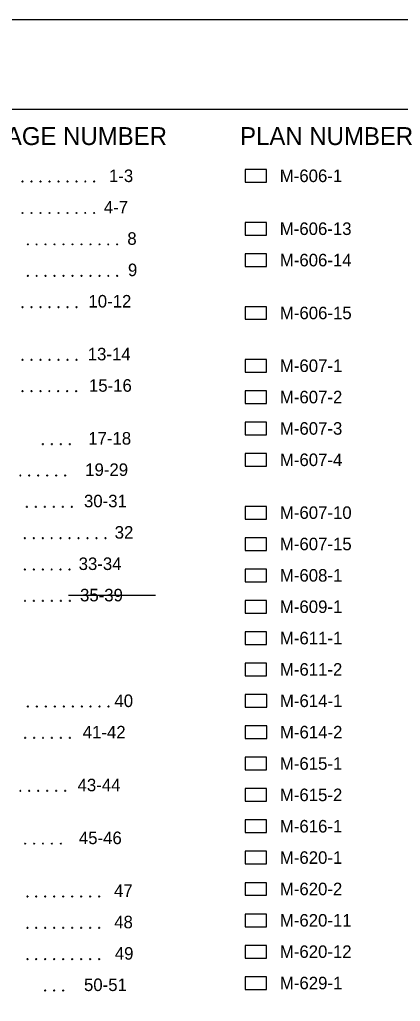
# Model space of a CAD drawing. Extents: x 0 to 1.42, y 0 to 0.92.
# Drawn here: x 0.4322 to 0.6093, y 0.4598 to 0.9167 of the extents above; entities that cross this region are included whole.
import ezdxf

# ---------------------------------------------------------------- set-up
doc = ezdxf.new("R2010")
doc.units = 0
for name, color, linetype in [('DRAFT_Text-Notes', 7, 'Continuous'), ('DRAFT_Text-Titles', 7, 'Continuous'), ('SHEET_Lines', 7, 'Continuous'), ('SHEET_Plot Boundary', 7, 'Continuous')]:
    doc.layers.add(name, color=color, linetype=linetype)

msp = doc.modelspace()

# ---------------------------------------------------------------- linework, layer by layer
at = {"layer": 'DRAFT_Text-Notes'}
for centre in [(0.43359, 0.84128), (0.43776, 0.84128), (0.44192, 0.84128), (0.44609, 0.84128), (0.45026, 0.84128), (0.45442, 0.84128), (0.45859, 0.84128), (0.46276, 0.84128), (0.46692, 0.84128), (0.43359, 0.82669), (0.43776, 0.82669), (0.44192, 0.82669), (0.44609, 0.82669), (0.45026, 0.82669), (0.45442, 0.82669), (0.45859, 0.82669), (0.46276, 0.82669), (0.46692, 0.82669), (0.43596, 0.8121), (0.44013, 0.8121), (0.44429, 0.8121), (0.44846, 0.8121), (0.45263, 0.8121), (0.45679, 0.8121), (0.46096, 0.8121), (0.46513, 0.8121), (0.46929, 0.8121), (0.47346, 0.8121), (0.47763, 0.8121), (0.43596, 0.79751), (0.44013, 0.79751), (0.44429, 0.79751), (0.44846, 0.79751), (0.45263, 0.79751), (0.45679, 0.79751), (0.46096, 0.79751), (0.46513, 0.79751), (0.46929, 0.79751), (0.47346, 0.79751), (0.47763, 0.79751), (0.43359, 0.78292), (0.43776, 0.78292), (0.44192, 0.78292), (0.44609, 0.78292), (0.45026, 0.78292), (0.45442, 0.78292), (0.45859, 0.78292), (0.43359, 0.75832), (0.43776, 0.75832), (0.44192, 0.75832), (0.44609, 0.75832), (0.45026, 0.75832), (0.45442, 0.75832), (0.45859, 0.75832), (0.43352, 0.74373), (0.43769, 0.74373), (0.44185, 0.74373), (0.44602, 0.74373), (0.45019, 0.74373), (0.45435, 0.74373), (0.45852, 0.74373), (0.44306, 0.71914), (0.44722, 0.71914), (0.45139, 0.71914), (0.45556, 0.71914), (0.43253, 0.70455), (0.4367, 0.70455), (0.44086, 0.70455), (0.44503, 0.70455), (0.4492, 0.70455), (0.45336, 0.70455), (0.43561, 0.68996), (0.43978, 0.68996), (0.44394, 0.68996), (0.44811, 0.68996), (0.45228, 0.68996), (0.45644, 0.68996), (0.4346, 0.67536), (0.43877, 0.67536), (0.44293, 0.67536), (0.4471, 0.67536), (0.45127, 0.67536), (0.45543, 0.67536), (0.4596, 0.67536), (0.46377, 0.67536), (0.46793, 0.67536), (0.4721, 0.67536), (0.4346, 0.66077), (0.43877, 0.66077), (0.44293, 0.66077), (0.4471, 0.66077), (0.45127, 0.66077), (0.45543, 0.66077), (0.43471, 0.64618), (0.43887, 0.64618), (0.44304, 0.64618), (0.44721, 0.64618), (0.45137, 0.64618), (0.45554, 0.64618), (0.43607, 0.597), (0.44023, 0.597), (0.4444, 0.597), (0.44857, 0.597), (0.45273, 0.597), (0.4569, 0.597), (0.46107, 0.597), (0.46523, 0.597), (0.4694, 0.597), (0.47357, 0.597), (0.43474, 0.5824), (0.43891, 0.5824), (0.44307, 0.5824), (0.44724, 0.5824), (0.45141, 0.5824), (0.45557, 0.5824), (0.43253, 0.55781), (0.4367, 0.55781), (0.44087, 0.55781), (0.44503, 0.55781), (0.4492, 0.55781), (0.45337, 0.55781), (0.43474, 0.53322), (0.43891, 0.53322), (0.44307, 0.53322), (0.44724, 0.53322), (0.45141, 0.53322), (0.4358, 0.50863), (0.43996, 0.50863), (0.44413, 0.50863), (0.4483, 0.50863), (0.45246, 0.50863), (0.45663, 0.50863), (0.4608, 0.50863), (0.46496, 0.50863), (0.46913, 0.50863), (0.4358, 0.49404), (0.43996, 0.49404), (0.44413, 0.49404), (0.4483, 0.49404), (0.45246, 0.49404), (0.45663, 0.49404), (0.4608, 0.49404), (0.46496, 0.49404), (0.46913, 0.49404), (0.4358, 0.47944), (0.43996, 0.47944), (0.44413, 0.47944), (0.4483, 0.47944), (0.45246, 0.47944), (0.45663, 0.47944), (0.4608, 0.47944), (0.46496, 0.47944), (0.46913, 0.47944), (0.44413, 0.46485), (0.4483, 0.46485), (0.45246, 0.46485)]:
    msp.add_circle(centre, 0.000208, dxfattribs=at)
for centre, start, end in [((0.43359, 0.84128), 0, 180), ((0.43359, 0.84128), 180, 0), ((0.43776, 0.84128), 0, 180), ((0.43776, 0.84128), 180, 0), ((0.44192, 0.84128), 0, 180), ((0.44192, 0.84128), 180, 0), ((0.44609, 0.84128), 0, 180), ((0.44609, 0.84128), 180, 0), ((0.45026, 0.84128), 0, 180), ((0.45026, 0.84128), 180, 0), ((0.45442, 0.84128), 0, 180), ((0.45442, 0.84128), 180, 0), ((0.45859, 0.84128), 0, 180), ((0.45859, 0.84128), 180, 0), ((0.46276, 0.84128), 0, 180), ((0.46276, 0.84128), 180, 0), ((0.46692, 0.84128), 0, 180), ((0.46692, 0.84128), 180, 0), ((0.43359, 0.82669), 0, 180), ((0.43776, 0.82669), 0, 180), ((0.44192, 0.82669), 0, 180), ((0.44609, 0.82669), 0, 180), ((0.45026, 0.82669), 0, 180), ((0.45442, 0.82669), 0, 180), ((0.45859, 0.82669), 0, 180), ((0.46276, 0.82669), 0, 180), ((0.46692, 0.82669), 0, 180), ((0.43359, 0.82669), 180, 0), ((0.43776, 0.82669), 180, 0), ((0.44192, 0.82669), 180, 0), ((0.44609, 0.82669), 180, 0), ((0.45026, 0.82669), 180, 0), ((0.45442, 0.82669), 180, 0), ((0.45859, 0.82669), 180, 0), ((0.46276, 0.82669), 180, 0), ((0.46692, 0.82669), 180, 0), ((0.43596, 0.8121), 0, 180), ((0.43596, 0.8121), 180, 0), ((0.44013, 0.8121), 0, 180), ((0.44013, 0.8121), 180, 0), ((0.44429, 0.8121), 0, 180), ((0.44429, 0.8121), 180, 0), ((0.44846, 0.8121), 0, 180), ((0.44846, 0.8121), 180, 0), ((0.45263, 0.8121), 0, 180), ((0.45263, 0.8121), 180, 0), ((0.45679, 0.8121), 0, 180), ((0.45679, 0.8121), 180, 0), ((0.46096, 0.8121), 0, 180), ((0.46096, 0.8121), 180, 0), ((0.46513, 0.8121), 0, 180), ((0.46513, 0.8121), 180, 0), ((0.46929, 0.8121), 0, 180), ((0.46929, 0.8121), 180, 0), ((0.47346, 0.8121), 0, 180), ((0.47346, 0.8121), 180, 0), ((0.47763, 0.8121), 0, 180), ((0.47763, 0.8121), 180, 0), ((0.43596, 0.79751), 0, 180), ((0.43596, 0.79751), 180, 0), ((0.44013, 0.79751), 0, 180), ((0.44013, 0.79751), 180, 0), ((0.44429, 0.79751), 0, 180), ((0.44429, 0.79751), 180, 0), ((0.44846, 0.79751), 0, 180), ((0.44846, 0.79751), 180, 0), ((0.45263, 0.79751), 0, 180), ((0.45263, 0.79751), 180, 0), ((0.45679, 0.79751), 0, 180), ((0.45679, 0.79751), 180, 0), ((0.46096, 0.79751), 0, 180), ((0.46096, 0.79751), 180, 0), ((0.46513, 0.79751), 0, 180), ((0.46513, 0.79751), 180, 0), ((0.46929, 0.79751), 0, 180), ((0.46929, 0.79751), 180, 0), ((0.47346, 0.79751), 0, 180), ((0.47346, 0.79751), 180, 0), ((0.47763, 0.79751), 0, 180), ((0.47763, 0.79751), 180, 0), ((0.43359, 0.78292), 0, 180), ((0.43359, 0.78292), 180, 0), ((0.43776, 0.78292), 0, 180), ((0.43776, 0.78292), 180, 0), ((0.44192, 0.78292), 0, 180), ((0.44192, 0.78292), 180, 0), ((0.44609, 0.78292), 0, 180), ((0.44609, 0.78292), 180, 0), ((0.45026, 0.78292), 0, 180), ((0.45026, 0.78292), 180, 0), ((0.45442, 0.78292), 0, 180), ((0.45442, 0.78292), 180, 0), ((0.45859, 0.78292), 0, 180), ((0.45859, 0.78292), 180, 0), ((0.43359, 0.75832), 0, 180), ((0.43776, 0.75832), 0, 180), ((0.44192, 0.75832), 0, 180), ((0.44609, 0.75832), 0, 180), ((0.45026, 0.75832), 0, 180), ((0.45442, 0.75832), 0, 180), ((0.45859, 0.75832), 0, 180), ((0.43359, 0.75832), 180, 0), ((0.43776, 0.75832), 180, 0), ((0.44192, 0.75832), 180, 0), ((0.44609, 0.75832), 180, 0), ((0.45026, 0.75832), 180, 0), ((0.45442, 0.75832), 180, 0), ((0.45859, 0.75832), 180, 0), ((0.43352, 0.74373), 0, 180), ((0.43352, 0.74373), 180, 0), ((0.43769, 0.74373), 0, 180), ((0.43769, 0.74373), 180, 0), ((0.44185, 0.74373), 0, 180), ((0.44185, 0.74373), 180, 0), ((0.44602, 0.74373), 0, 180), ((0.44602, 0.74373), 180, 0), ((0.45019, 0.74373), 0, 180), ((0.45019, 0.74373), 180, 0), ((0.45435, 0.74373), 0, 180), ((0.45435, 0.74373), 180, 0), ((0.45852, 0.74373), 0, 180), ((0.45852, 0.74373), 180, 0), ((0.44306, 0.71914), 0, 180), ((0.44306, 0.71914), 180, 0), ((0.44722, 0.71914), 0, 180), ((0.44722, 0.71914), 180, 0), ((0.45139, 0.71914), 0, 180), ((0.45139, 0.71914), 180, 0), ((0.45556, 0.71914), 0, 180), ((0.45556, 0.71914), 180, 0), ((0.43253, 0.70455), 0, 180), ((0.43253, 0.70455), 180, 0), ((0.4367, 0.70455), 0, 180), ((0.4367, 0.70455), 180, 0), ((0.44086, 0.70455), 0, 180), ((0.44086, 0.70455), 180, 0), ((0.44503, 0.70455), 0, 180), ((0.44503, 0.70455), 180, 0), ((0.4492, 0.70455), 0, 180), ((0.4492, 0.70455), 180, 0), ((0.45336, 0.70455), 0, 180), ((0.45336, 0.70455), 180, 0), ((0.43561, 0.68996), 0, 180), ((0.43561, 0.68996), 180, 0), ((0.43978, 0.68996), 0, 180), ((0.43978, 0.68996), 180, 0), ((0.44394, 0.68996), 0, 180), ((0.44394, 0.68996), 180, 0), ((0.44811, 0.68996), 0, 180), ((0.44811, 0.68996), 180, 0), ((0.45228, 0.68996), 0, 180), ((0.45228, 0.68996), 180, 0), ((0.45644, 0.68996), 0, 180), ((0.45644, 0.68996), 180, 0), ((0.4346, 0.67536), 0, 180), ((0.4346, 0.67536), 180, 0), ((0.43877, 0.67536), 0, 180), ((0.43877, 0.67536), 180, 0), ((0.44293, 0.67536), 0, 180), ((0.44293, 0.67536), 180, 0), ((0.4471, 0.67536), 0, 180), ((0.4471, 0.67536), 180, 0), ((0.45127, 0.67536), 0, 180), ((0.45127, 0.67536), 180, 0), ((0.45543, 0.67536), 0, 180), ((0.45543, 0.67536), 180, 0), ((0.4596, 0.67536), 0, 180), ((0.4596, 0.67536), 180, 0), ((0.46377, 0.67536), 0, 180), ((0.46377, 0.67536), 180, 0), ((0.46793, 0.67536), 0, 180), ((0.46793, 0.67536), 180, 0), ((0.4721, 0.67536), 0, 180), ((0.4721, 0.67536), 180, 0), ((0.4346, 0.66077), 0, 180), ((0.4346, 0.66077), 180, 0), ((0.43877, 0.66077), 0, 180), ((0.43877, 0.66077), 180, 0), ((0.44293, 0.66077), 0, 180), ((0.44293, 0.66077), 180, 0), ((0.4471, 0.66077), 0, 180), ((0.4471, 0.66077), 180, 0), ((0.45127, 0.66077), 0, 180), ((0.45127, 0.66077), 180, 0), ((0.45543, 0.66077), 0, 180), ((0.45543, 0.66077), 180, 0), ((0.43471, 0.64618), 0, 180), ((0.43471, 0.64618), 180, 0), ((0.43887, 0.64618), 0, 180), ((0.43887, 0.64618), 180, 0), ((0.44304, 0.64618), 0, 180), ((0.44304, 0.64618), 180, 0), ((0.44721, 0.64618), 0, 180), ((0.44721, 0.64618), 180, 0), ((0.45137, 0.64618), 0, 180), ((0.45137, 0.64618), 180, 0), ((0.45554, 0.64618), 0, 180), ((0.45554, 0.64618), 180, 0), ((0.43607, 0.597), 0, 180), ((0.43607, 0.597), 180, 0), ((0.44023, 0.597), 0, 180), ((0.44023, 0.597), 180, 0), ((0.4444, 0.597), 0, 180), ((0.4444, 0.597), 180, 0), ((0.44857, 0.597), 0, 180), ((0.44857, 0.597), 180, 0), ((0.45273, 0.597), 0, 180), ((0.45273, 0.597), 180, 0), ((0.4569, 0.597), 0, 180), ((0.4569, 0.597), 180, 0), ((0.46107, 0.597), 0, 180), ((0.46107, 0.597), 180, 0), ((0.46523, 0.597), 0, 180), ((0.46523, 0.597), 180, 0), ((0.4694, 0.597), 0, 180), ((0.4694, 0.597), 180, 0), ((0.47357, 0.597), 0, 180), ((0.47357, 0.597), 180, 0), ((0.43474, 0.5824), 0, 180), ((0.43474, 0.5824), 180, 0), ((0.43891, 0.5824), 0, 180), ((0.43891, 0.5824), 180, 0), ((0.44307, 0.5824), 0, 180), ((0.44307, 0.5824), 180, 0), ((0.44724, 0.5824), 0, 180), ((0.44724, 0.5824), 180, 0), ((0.45141, 0.5824), 0, 180), ((0.45141, 0.5824), 180, 0), ((0.45557, 0.5824), 0, 180), ((0.45557, 0.5824), 180, 0), ((0.43253, 0.55781), 0, 180), ((0.43253, 0.55781), 180, 0), ((0.4367, 0.55781), 0, 180), ((0.4367, 0.55781), 180, 0), ((0.44087, 0.55781), 0, 180), ((0.44087, 0.55781), 180, 0), ((0.44503, 0.55781), 0, 180), ((0.44503, 0.55781), 180, 0), ((0.4492, 0.55781), 0, 180), ((0.4492, 0.55781), 180, 0), ((0.45337, 0.55781), 0, 180), ((0.45337, 0.55781), 180, 0), ((0.43474, 0.53322), 0, 180), ((0.43474, 0.53322), 180, 0), ((0.43891, 0.53322), 0, 180), ((0.43891, 0.53322), 180, 0), ((0.44307, 0.53322), 0, 180), ((0.44307, 0.53322), 180, 0), ((0.44724, 0.53322), 0, 180), ((0.44724, 0.53322), 180, 0), ((0.45141, 0.53322), 0, 180), ((0.45141, 0.53322), 180, 0), ((0.4358, 0.50863), 0, 180), ((0.4358, 0.50863), 180, 0), ((0.43996, 0.50863), 0, 180), ((0.43996, 0.50863), 180, 0), ((0.44413, 0.50863), 0, 180), ((0.44413, 0.50863), 180, 0), ((0.4483, 0.50863), 0, 180), ((0.4483, 0.50863), 180, 0), ((0.45246, 0.50863), 0, 180), ((0.45246, 0.50863), 180, 0), ((0.45663, 0.50863), 0, 180), ((0.45663, 0.50863), 180, 0), ((0.4608, 0.50863), 0, 180), ((0.4608, 0.50863), 180, 0), ((0.46496, 0.50863), 0, 180), ((0.46496, 0.50863), 180, 0), ((0.46913, 0.50863), 0, 180), ((0.46913, 0.50863), 180, 0), ((0.4358, 0.49404), 0, 180), ((0.4358, 0.49404), 180, 0), ((0.43996, 0.49404), 0, 180), ((0.43996, 0.49404), 180, 0), ((0.44413, 0.49404), 0, 180), ((0.44413, 0.49404), 180, 0), ((0.4483, 0.49404), 0, 180), ((0.4483, 0.49404), 180, 0), ((0.45246, 0.49404), 0, 180), ((0.45246, 0.49404), 180, 0), ((0.45663, 0.49404), 0, 180), ((0.45663, 0.49404), 180, 0), ((0.4608, 0.49404), 0, 180), ((0.4608, 0.49404), 180, 0), ((0.46496, 0.49404), 0, 180), ((0.46496, 0.49404), 180, 0), ((0.46913, 0.49404), 0, 180), ((0.46913, 0.49404), 180, 0), ((0.4358, 0.47944), 0, 180), ((0.4358, 0.47944), 180, 0), ((0.43996, 0.47944), 0, 180), ((0.43996, 0.47944), 180, 0), ((0.44413, 0.47944), 0, 180), ((0.44413, 0.47944), 180, 0), ((0.4483, 0.47944), 0, 180), ((0.4483, 0.47944), 180, 0), ((0.45246, 0.47944), 0, 180), ((0.45246, 0.47944), 180, 0), ((0.45663, 0.47944), 0, 180), ((0.45663, 0.47944), 180, 0), ((0.4608, 0.47944), 0, 180), ((0.4608, 0.47944), 180, 0), ((0.46496, 0.47944), 0, 180), ((0.46496, 0.47944), 180, 0), ((0.46913, 0.47944), 0, 180), ((0.46913, 0.47944), 180, 0), ((0.44413, 0.46485), 0, 180), ((0.44413, 0.46485), 180, 0), ((0.4483, 0.46485), 0, 180), ((0.4483, 0.46485), 180, 0), ((0.45246, 0.46485), 0, 180), ((0.45246, 0.46485), 180, 0)]:
    msp.add_arc(centre, 0.000208, start, end, dxfattribs=at)
at = {"layer": 'DRAFT_Text-Titles'}
msp.add_line((0.45491, 0.64881), (0.49535, 0.64881), dxfattribs=at)
at = {"layer": 'SHEET_Lines'}
msp.add_lwpolyline([(0.08333, 0.875), (1.375, 0.875), (1.375, 0.125), (0.08333, 0.125)], close=True, dxfattribs=at)
for points in [[(0.53706, 0.84102), (0.54703, 0.84102), (0.54703, 0.84691), (0.53706, 0.84691), (0.53706, 0.84102)], [(0.53706, 0.8164), (0.54703, 0.8164), (0.54703, 0.82228), (0.53706, 0.82228), (0.53706, 0.8164)], [(0.53708, 0.8018), (0.54705, 0.8018), (0.54705, 0.80769), (0.53708, 0.80769), (0.53708, 0.8018)], [(0.53711, 0.77721), (0.54708, 0.77721), (0.54708, 0.7831), (0.53711, 0.7831), (0.53711, 0.77721)], [(0.53711, 0.75266), (0.54708, 0.75266), (0.54708, 0.75854), (0.53711, 0.75854), (0.53711, 0.75266)], [(0.53711, 0.73806), (0.54708, 0.73806), (0.54708, 0.74395), (0.53711, 0.74395), (0.53711, 0.73806)], [(0.53711, 0.72347), (0.54708, 0.72347), (0.54708, 0.72936), (0.53711, 0.72936), (0.53711, 0.72347)], [(0.53711, 0.70888), (0.54708, 0.70888), (0.54708, 0.71477), (0.53711, 0.71477), (0.53711, 0.70888)], [(0.53711, 0.68429), (0.54708, 0.68429), (0.54708, 0.69017), (0.53711, 0.69017), (0.53711, 0.68429)], [(0.53711, 0.66969), (0.54708, 0.66969), (0.54708, 0.67558), (0.53711, 0.67558), (0.53711, 0.66969)], [(0.53711, 0.6551), (0.54708, 0.6551), (0.54708, 0.66099), (0.53711, 0.66099), (0.53711, 0.6551)], [(0.53711, 0.64051), (0.54708, 0.64051), (0.54708, 0.6464), (0.53711, 0.6464), (0.53711, 0.64051)], [(0.53711, 0.62592), (0.54708, 0.62592), (0.54708, 0.6318), (0.53711, 0.6318), (0.53711, 0.62592)], [(0.53711, 0.61133), (0.54708, 0.61133), (0.54708, 0.61721), (0.53711, 0.61721), (0.53711, 0.61133)], [(0.53713, 0.59673), (0.5471, 0.59673), (0.5471, 0.60262), (0.53713, 0.60262), (0.53713, 0.59673)], [(0.53714, 0.58214), (0.54712, 0.58214), (0.54712, 0.58803), (0.53714, 0.58803), (0.53714, 0.58214)], [(0.5371, 0.56755), (0.54707, 0.56755), (0.54707, 0.57344), (0.5371, 0.57344), (0.5371, 0.56755)], [(0.5371, 0.55296), (0.54707, 0.55296), (0.54707, 0.55884), (0.5371, 0.55884), (0.5371, 0.55296)], [(0.5371, 0.53837), (0.54707, 0.53837), (0.54707, 0.54425), (0.5371, 0.54425), (0.5371, 0.53837)], [(0.5371, 0.52377), (0.54707, 0.52377), (0.54707, 0.52966), (0.5371, 0.52966), (0.5371, 0.52377)], [(0.5371, 0.50918), (0.54707, 0.50918), (0.54707, 0.51507), (0.5371, 0.51507), (0.5371, 0.50918)], [(0.5371, 0.49459), (0.54707, 0.49459), (0.54707, 0.50048), (0.5371, 0.50048), (0.5371, 0.49459)], [(0.5371, 0.48), (0.54707, 0.48), (0.54707, 0.48588), (0.5371, 0.48588), (0.5371, 0.48)], [(0.53711, 0.46541), (0.54708, 0.46541), (0.54708, 0.47129), (0.53711, 0.47129), (0.53711, 0.46541)]]:
    msp.add_lwpolyline(points, dxfattribs=at)
at = {"layer": 'SHEET_Plot Boundary'}
msp.add_lwpolyline([(0, 0.91667), (1.41667, 0.91667), (1.41667, 0), (0, 0)], close=True, dxfattribs=at)

# ---------------------------------------------------------------- texts
at = {"layer": 'DRAFT_Text-Notes'}
for s, height, p in [('1-3', 0.005833, (0.47376, 0.84108)), ('M-606-1', 0.005833, (0.55319, 0.84108)), ('4-7', 0.005833, (0.47137, 0.82648)), ('M-606-13', 0.005833, (0.55319, 0.81645)), ('8', 0.00583, (0.4823, 0.81189)), ('M-606-14', 0.005833, (0.55321, 0.80186)), ('9', 0.00583, (0.48258, 0.7973)), ('10-12', 0.005833, (0.46421, 0.78271)), ('M-606-15', 0.005833, (0.55324, 0.77726)), ('13-14', 0.005833, (0.46389, 0.75812)), ('M-607-1', 0.005833, (0.55324, 0.75271)), ('15-16', 0.005833, (0.46444, 0.74352)), ('M-607-2', 0.005833, (0.55324, 0.73812)), ('M-607-3', 0.005833, (0.55324, 0.72352)), ('17-18', 0.005833, (0.46412, 0.71893)), ('M-607-4', 0.005833, (0.55324, 0.70893)), ('19-29', 0.005833, (0.4627, 0.70434)), ('30-31', 0.005833, (0.46214, 0.68975)), ('M-607-10', 0.005833, (0.55324, 0.68434)), ('32', 0.005833, (0.47642, 0.67516)), ('M-607-15', 0.005833, (0.55324, 0.66975)), ('33-34', 0.005833, (0.45966, 0.66056)), ('M-608-1', 0.005833, (0.55324, 0.65516)), ('35-39', 0.005833, (0.4603, 0.64597)), ('M-609-1', 0.005833, (0.55324, 0.64056)), ('M-611-1', 0.005833, (0.55324, 0.62597)), ('M-611-2', 0.005833, (0.55324, 0.61138)), ('40', 0.005833, (0.47629, 0.59679)), ('M-614-1', 0.005833, (0.55326, 0.59679)), ('41-42', 0.005833, (0.46155, 0.5822)), ('M-614-2', 0.005833, (0.55327, 0.5822)), ('M-615-1', 0.005833, (0.55322, 0.5676)), ('43-44', 0.005833, (0.45916, 0.5576)), ('M-615-2', 0.005833, (0.55322, 0.55301)), ('M-616-1', 0.005833, (0.55322, 0.53842)), ('45-46', 0.005833, (0.45976, 0.53301)), ('M-620-1', 0.005833, (0.55322, 0.52383)), ('47', 0.005833, (0.4761, 0.50842)), ('M-620-2', 0.005833, (0.55322, 0.50924)), ('48', 0.005833, (0.47619, 0.49383)), ('M-620-11', 0.005833, (0.55322, 0.49464)), ('49', 0.005833, (0.47647, 0.47924)), ('M-620-12', 0.005833, (0.55322, 0.48005)), ('50-51', 0.005833, (0.46214, 0.46464)), ('M-629-1', 0.005833, (0.55324, 0.46546))]:
    msp.add_text(s, height=height, dxfattribs=at).set_placement(p)
at = {"layer": 'DRAFT_Text-Titles'}
for s, p in [('PAGE NUMBER', (0.41838, 0.85831)), ('PLAN NUMBER', (0.53473, 0.85831))]:
    msp.add_text(s, height=0.0083333, dxfattribs=at).set_placement(p)

doc.saveas('drawing.dxf')
